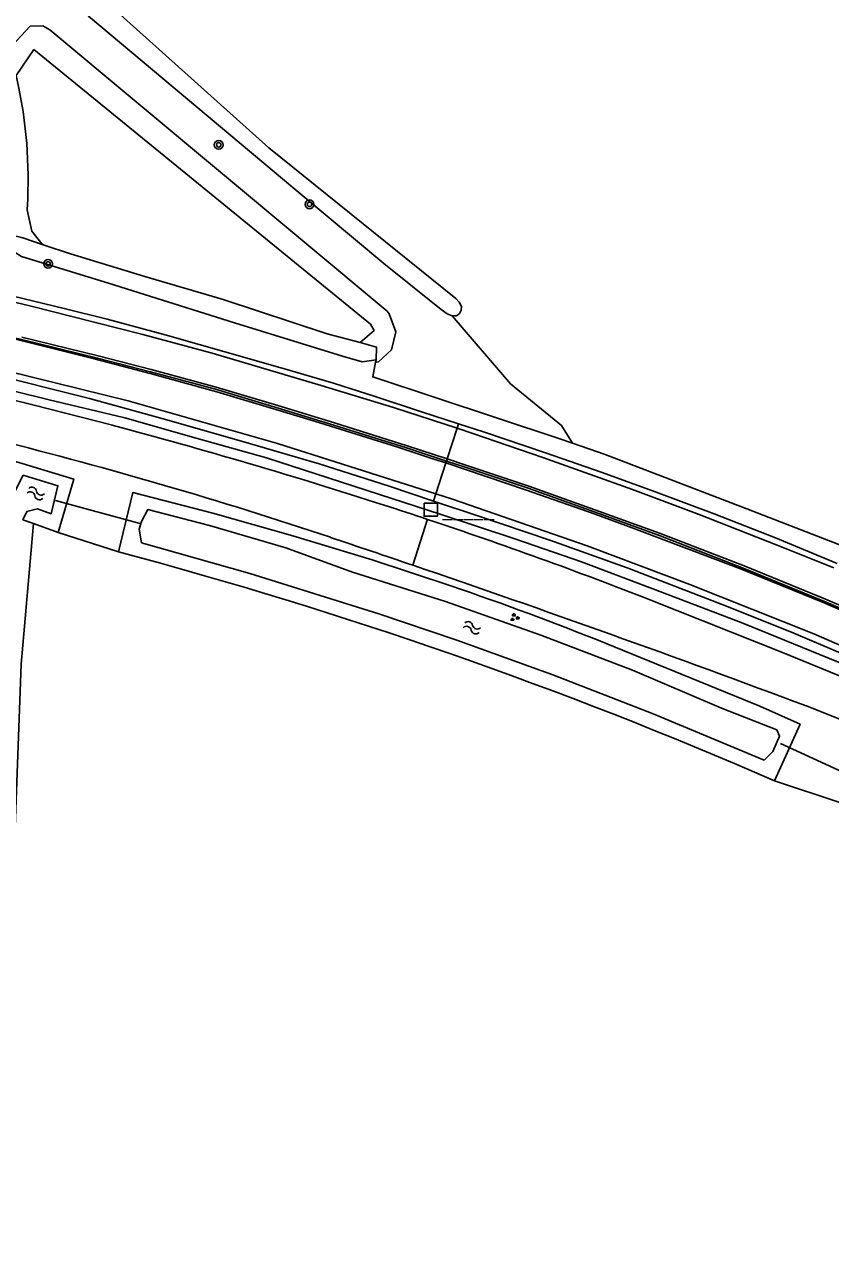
# Model space of a CAD drawing. Extents: x 124000 to 128010, y 398999 to 403000.
# Drawn here: x 125705.2 to 125778.3, y 402700.9 to 402811.8 of the extents above; entities that cross this region are included whole.
import ezdxf

# ---------------------------------------------------------------- set-up
doc = ezdxf.new("R2010")
doc.units = 0
for name, color, linetype in [('gg-knt-verharding', 7, 'Continuous'), ('gg-kntw-beschoeiing', 7, 'Continuous'), ('gg-kntw-bovenkant insteek waterloop', 7, 'Continuous'), ('gg-kntw-waterlijn', 7, 'Continuous'), ('gg-kwrk-duiker nz buis', 7, 'Continuous'), ('gt-grn-groengrens', 7, 'Continuous'), ('gt-grn-vlakafsluiter', 7, 'Continuous'), ('gt-symb-boom', 7, 'Continuous'), ('gt-symb-groenvak', 7, 'Continuous'), ('gt-symb-hm paal', 7, 'Continuous'), ('gt-symb-watersymbool', 7, 'Continuous'), ('gx-grn-maaiveld', 7, 'Continuous'), ('gx-knt-lijn weginrichtingselement', 7, 'Continuous')]:
    doc.layers.add(name, color=color, linetype=linetype)

# ---------------------------------------------------------------- blocks, each defined once
blk = doc.blocks.new('gt0-BOOM')
at = {"layer": 'gt-symb-boom'}
for radius in [0.4, 0.2]:
    blk.add_circle((0, 0), radius, dxfattribs=at)
blk = doc.blocks.new('gt0-WA')
at = {"layer": 'gt-symb-watersymbool'}
for centre, start, end in [((-0.32, 0.02), 28.0725, 151.9275), ((0.43, 0.42), 208.0725, 331.9275), ((-0.32, -0.43), 28.0725, 151.9275), ((0.43, -0.03), 208.0725, 331.9275)]:
    blk.add_arc(centre, 0.425, start, end, dxfattribs=at)
blk = doc.blocks.new('gt0-GRVAK')
at = {"layer": 'gt-symb-groenvak'}
for p, q in [((-0.11, 0.19), (-0.23, 0.24)), ((-0.18, 0.15), (0.09, 0.15)), ((-0.09, 0.21), (-0.16, 0.32)), ((-0.05, 0.21), (-0.05, 0.39)), ((0, 0.21), (0.06, 0.32)), ((0.01, 0.19), (0.13, 0.24)), ((0.26, -0.05), (0.2, 0.06)), ((0.3, -0.05), (0.3, 0.13)), ((0.35, -0.05), (0.41, 0.06)), ((-0.25, -0.23), (-0.36, -0.18)), ((-0.32, -0.26), (-0.05, -0.26)), ((-0.23, -0.21), (-0.29, -0.1)), ((-0.18, -0.2), (-0.18, -0.02)), ((-0.14, -0.21), (-0.07, -0.1)), ((-0.12, -0.23), (0, -0.18)), ((0.24, -0.07), (0.12, -0.02)), ((0.17, -0.11), (0.44, -0.11)), ((0.37, -0.07), (0.49, -0.02))]:
    blk.add_line(p, q, dxfattribs=at)
blk = doc.blocks.new('gt0-HMpaal')
at = {"layer": 'gt-symb-hm paal'}
blk.add_lwpolyline([(-0.6, 0.6), (0.6, 0.6), (0.6, -0.6), (-0.6, -0.6)], close=True, dxfattribs=at)

msp = doc.modelspace()

# ---------------------------------------------------------------- linework, layer by layer
at = {"layer": 'gg-knt-verharding'}
for points in [[(125686.31, 402781.86), (125693.47, 402780.31), (125698.72, 402779.11), (125705.96, 402777.35), (125713.18, 402775.49)], [(125794.12, 402742.03), (125791.31, 402743.35), (125783.8, 402746.81), (125780.02, 402748.47), (125776.18, 402749.99)]]:
    msp.add_lwpolyline(points, dxfattribs=at)
for centre, radius, start, end in [((125584.29, 402291.76), 500.6, 72.1411, 75.0806), ((125603.77, 402379.05), 407.3, 71.5095, 75.9416)]:
    msp.add_arc(centre, radius, start, end, dxfattribs=at)
at = {"layer": 'gg-kntw-beschoeiing'}
msp.add_lwpolyline([(125783.1, 402765.34), (125782.45, 402763.34), (125780.34, 402764.17), (125779.03, 402764.67), (125770.71, 402767.89), (125757.86, 402772.83), (125754.9, 402773.85), (125753.66, 402774.27), (125736.79, 402779.87)], dxfattribs=at)
at = {"layer": 'gg-kntw-bovenkant insteek waterloop'}
msp.add_line((125708.25, 402765.77), (125706.02, 402766.56), dxfattribs=at)
for points in [[(125702.38, 402767.84), (125703.99, 402772.33), (125709.67, 402770.6), (125708.25, 402765.77)], [(125713.73, 402763.99), (125715.02, 402769.38), (125722.29, 402767.5), (125729.53, 402765.46), (125736.72, 402763.27), (125743.86, 402760.92)], [(125706.02, 402766.56), (125704.91, 402753.82), (125701.91, 402673.34), (125700.52, 402637.23), (125699.06, 402595.95), (125694.6, 402480.1), (125670.64, 402481.33), (125646.27, 402482.57), (125619.88, 402483.83), (125593.98, 402485.31)], [(125757.95, 402755.69), (125771.86, 402750), (125775.52, 402748.36), (125773.2, 402743.23)]]:
    msp.add_lwpolyline(points, dxfattribs=at)
for centre, radius, start, end in [((125606.87, 402362.22), 415.74, 66.4158, 75.1051), ((125652.83, 402493.97), 282.04, 68.1175, 71.1711)]:
    msp.add_arc(centre, radius, start, end, dxfattribs=at)
at = {"layer": 'gg-kntw-waterlijn'}
for points in [[(125703.86, 402767.32), (125703.99, 402768.8), (125705.1, 402770.95), (125708.24, 402769.99), (125707.63, 402767.45), (125706.4, 402767.91), (125705.43, 402767.66), (125705.05, 402766.9)], [(125715.83, 402764.82), (125715.62, 402766.07), (125715.81, 402766.74), (125716.38, 402767.84), (125721.99, 402766.39), (125728.9, 402764.36), (125734.95, 402762.17), (125743.39, 402759.49), (125752.01, 402756.45), (125760.34, 402753.26), (125768.41, 402749.83), (125773.41, 402747.87)], [(125715.83, 402764.82), (125725.64, 402762.04), (125737.34, 402758.38), (125744.4, 402755.98), (125753.1, 402752.84), (125762.19, 402749.31), (125772.26, 402745.11), (125773.05, 402745.88), (125773.66, 402747.29), (125773.41, 402747.87)]]:
    msp.add_lwpolyline(points, dxfattribs=at)
at = {"layer": 'gg-kwrk-duiker nz buis'}
for p, q in [((125715.78, 402766.53), (125708.03, 402768.66)), ((125780.8, 402743.38), (125773.74, 402746.62))]:
    msp.add_line(p, q, dxfattribs=at)
at = {"layer": 'gt-grn-groengrens'}
for p, q in [((125708.25, 402765.77), (125713.73, 402763.99)), ((125773.2, 402743.23), (125779.23, 402741.23))]:
    msp.add_line(p, q, dxfattribs=at)
at = {"layer": 'gt-grn-vlakafsluiter'}
msp.add_line((125706.02, 402766.56), (125705.05, 402766.9), dxfattribs=at)
at = {"layer": 'gx-grn-maaiveld'}
for p, q in [((125737.08, 402781.41), (125737.04, 402781.21)), ((125740.42, 402762.8), (125741.76, 402766.95))]:
    msp.add_line(p, q, dxfattribs=at)
for points in [[(125708.06, 402818), (125727.37, 402800.65), (125744.33, 402786.97), (125744.62, 402786.66), (125744.82, 402786.26), (125744.8, 402785.93), (125744.66, 402785.62), (125744.39, 402785.41), (125743.98, 402785.4)], [(125743.98, 402785.4), (125743.54, 402785.59), (125742.99, 402785.97), (125737.8, 402790.14), (125729.73, 402796.89), (125711.02, 402812.58), (125706.84, 402816.91)], [(125737.04, 402781.21), (125737.31, 402781.24), (125738.48, 402782.33), (125738.89, 402783.97), (125738.28, 402785.6), (125738.09, 402785.82), (125707.5, 402811.35), (125706.88, 402811.7), (125705.73, 402811.69), (125702.92, 402808.68), (125703.2, 402806.28), (125703.55, 402802.17), (125703.77, 402798.05), (125703.82, 402795.98), (125703.83, 402794.99), (125703.93, 402792.76)], [(125735.63, 402782.98), (125736.9, 402784.08), (125736.58, 402784.64), (125706.07, 402809.55), (125704.46, 402807.2), (125704.71, 402806.06), (125705.08, 402803.94), (125705.41, 402801.07), (125705.54, 402798.19), (125705.5, 402796.03), (125705.45, 402795.03), (125705.89, 402793.09), (125706.78, 402791.95), (125707.01, 402791.82)], [(125646.7, 402797.63), (125650, 402797.27), (125654.78, 402796.62), (125660.55, 402795.82), (125667.42, 402794.64), (125674.88, 402793.39), (125681.32, 402792.2), (125689.11, 402790.64), (125696.43, 402788.97), (125702.28, 402787.64), (125708.82, 402786.08), (125712.72, 402785.1), (125717.95, 402783.67), (125724.13, 402781.94), (125729.29, 402780.44), (125733.22, 402779.3), (125736.99, 402778.1), (125741.21, 402776.71), (125744.57, 402775.62)], [(125646.28, 402794.06), (125649.4, 402793.66), (125658.3, 402792.43), (125666.13, 402791.16), (125673.77, 402789.85), (125684.8, 402787.78), (125696.49, 402785.27), (125704.93, 402783.27), (125711.84, 402781.58), (125716.65, 402780.33), (125722.54, 402778.76), (125728.12, 402777.07), (125733.25, 402775.5), (125739.83, 402773.43), (125743.47, 402772.24)], [(125707.01, 402791.82), (125705.05, 402792.47), (125703.93, 402792.76)], [(125737.08, 402781.41), (125735.83, 402781.25), (125734.04, 402781.75), (125724.25, 402784.78), (125712.84, 402788.37), (125704.94, 402790.8), (125704.36, 402791.14), (125703.92, 402791.84)], [(125707.01, 402791.82), (125709.37, 402791.04), (125716.12, 402788.96), (125723.22, 402786.89), (125732.65, 402783.78), (125735.63, 402782.98)], [(125645.84, 402790.36), (125647.34, 402790.2), (125653.29, 402789.35), (125658.67, 402788.56), (125665.56, 402787.53), (125672.37, 402786.33), (125679.74, 402785.01), (125687.7, 402783.39), (125695.01, 402781.71), (125701.69, 402780.26), (125711.09, 402777.9), (125717.79, 402776.06), (125724.89, 402774.05), (125731.94, 402771.99), (125738.28, 402769.96), (125742.3, 402768.61)], [(125835.97, 402726.23), (125816.7, 402736.12), (125801.6, 402743.68), (125794.5, 402747.12), (125782.63, 402752.51), (125770.34, 402757.52), (125763.06, 402760.31), (125755.7, 402763.09), (125749.65, 402765.18), (125743, 402767.4), (125727.14, 402772.52), (125720.79, 402774.32), (125714.31, 402776.15), (125707.44, 402777.79), (125695.44, 402780.75), (125690.5, 402781.86), (125684.55, 402783.09), (125677.33, 402784.51), (125670.08, 402785.8), (125655.26, 402788.18), (125647.34, 402789.19), (125644.37, 402789.56)], [(125743.98, 402785.4), (125749.28, 402779.24), (125753.9, 402775.47), (125754.9, 402773.85)], [(125735.63, 402782.98), (125737.12, 402782.58), (125737.08, 402781.41)], [(125737.04, 402781.21), (125736.79, 402779.87), (125753.66, 402774.27), (125754.9, 402773.85)], [(125744.57, 402775.62), (125744.43, 402775.21), (125743.53, 402772.43), (125743.47, 402772.24)], [(125744.57, 402775.62), (125746.81, 402774.88), (125752.45, 402772.97), (125757.59, 402771.21), (125762.48, 402769.41), (125767.73, 402767.45), (125773.28, 402765.26), (125778.9, 402762.95)], [(125779.03, 402764.67), (125770.71, 402767.89), (125757.86, 402772.83), (125754.9, 402773.85)], [(125742.3, 402768.61), (125742.51, 402769.26), (125743.41, 402772.06), (125743.47, 402772.24)], [(125743.47, 402772.24), (125745.16, 402771.68), (125750.88, 402769.77), (125757.27, 402767.49), (125762.7, 402765.5), (125770.37, 402762.53), (125777.75, 402759.51), (125787.11, 402755.54), (125797.77, 402750.6), (125805.21, 402747.08), (125814.64, 402742.36), (125823.42, 402737.87), (125834.29, 402732.25), (125834.91, 402731.93)], [(125833.28, 402728.78), (125830.94, 402729.94), (125827.85, 402731.53), (125818.44, 402736.37), (125808.43, 402741.48), (125801.44, 402744.89), (125795.21, 402747.8), (125786.89, 402751.57), (125780.65, 402754.21), (125774.97, 402756.63), (125768.84, 402759.07), (125759.84, 402762.55), (125752.84, 402765.05), (125746.32, 402767.27), (125742.3, 402768.61)], [(125762, 402759.62), (125773.93, 402754.88), (125785.81, 402750.01), (125788.62, 402748.81), (125796.93, 402744.96), (125802.44, 402742.33), (125807.92, 402739.64), (125835.64, 402725.57)]]:
    msp.add_lwpolyline(points, dxfattribs=at)
for centre, radius, start, end in [((125598.26, 402335.59), 454.6, 71.6, 72.1234), ((125608.44, 402366.84), 421.73, 68.6463, 71.5712), ((125311.78, 401506.37), 1327.52, 71.16279, 71.50301), ((125327.67, 401553.48), 1277.81, 69.45169, 71.15503)]:
    msp.add_arc(centre, radius, start, end, dxfattribs=at)
at = {"layer": 'gx-knt-lijn weginrichtingselement'}
for points in [[(125787.96, 402751.7), (125776.76, 402756.56), (125765.53, 402761.04), (125756.22, 402764.54), (125744.02, 402768.78), (125742.51, 402769.26), (125728.15, 402773.82), (125714.61, 402777.71), (125699.15, 402781.51), (125679.92, 402785.55), (125667.09, 402787.88), (125649.45, 402790.53), (125646.2, 402790.97), (125640.64, 402791.58), (125631.54, 402792.4), (125619.81, 402793.25), (125607.95, 402793.91), (125589.96, 402794.42), (125583.91, 402794.48)], [(125697.11, 402788.36), (125705.93, 402786.26), (125709.5, 402785.36), (125715.94, 402783.71), (125722.23, 402782.01), (125732.12, 402779.09), (125738.65, 402777.08), (125744.43, 402775.21), (125745.86, 402774.74), (125752.21, 402772.56), (125760.33, 402769.67), (125766.38, 402767.4), (125773.44, 402764.62), (125778.57, 402762.56)], [(125787.12, 402755.3), (125777.57, 402759.45), (125770.11, 402762.46), (125760.29, 402766.19), (125756.87, 402767.46), (125750.71, 402769.6), (125743.41, 402772.06), (125742.33, 402772.42), (125739.07, 402773.51), (125731.5, 402775.86), (125728.01, 402776.92), (125722.66, 402778.51), (125716.6, 402780.17), (125711.53, 402781.5), (125704.28, 402783.32)], [(125704.97, 402783.47), (125711.89, 402781.77), (125716.71, 402780.53), (125722.59, 402778.95), (125728.18, 402777.26), (125733.31, 402775.7), (125739.89, 402773.62), (125743.53, 402772.43), (125745.23, 402771.87), (125750.94, 402769.96), (125757.34, 402767.67), (125762.77, 402765.69), (125770.44, 402762.72), (125777.83, 402759.7), (125787.19, 402755.72)]]:
    msp.add_lwpolyline(points, dxfattribs=at)

# ---------------------------------------------------------------- block references
at = {"layer": 'gt-symb-boom'}
for p in [(125722.82, 402800.92), (125731.05, 402795.52), (125707.35, 402790.12)]:
    msp.add_blockref('gt0-BOOM', p, dxfattribs=at)
at = {"layer": 'gt-symb-groenvak'}
msp.add_blockref('gt0-GRVAK', (125749.62, 402758.05), dxfattribs=at)
at = {"layer": 'gt-symb-hm paal'}
msp.add_blockref('gt0-HMpaal', (125742.04, 402767.83), dxfattribs=at)
at = {"layer": 'gt-symb-watersymbool'}
for p, rotation in [((125706.18, 402769.32), -19.50357322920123), ((125745.72, 402757.14), -16.984732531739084)]:
    msp.add_blockref('gt0-WA', p, dxfattribs=dict(at, rotation=rotation))

# ---------------------------------------------------------------- texts
at = {"layer": 'gt-symb-hm paal'}
msp.add_text('_____', height=1.25, dxfattribs=at).set_placement((125743.13, 402767.22))

doc.saveas('drawing.dxf')
